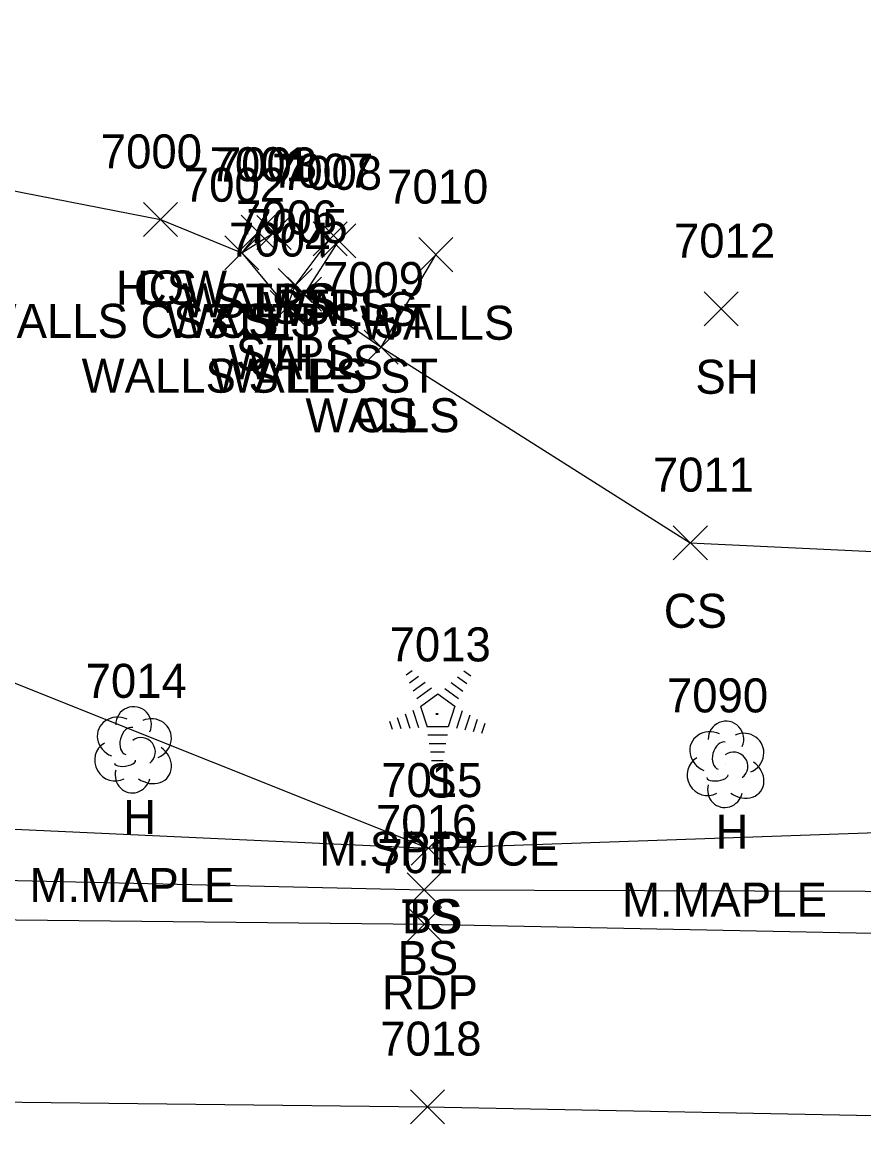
# Model space of a CAD drawing. Extents: x 1443912 to 1445411, y 621446 to 623693.
# Drawn here: x 1445082.7 to 1445132.2, y 622576.7 to 622641.6 of the extents above; entities that cross this region are included whole.
import ezdxf

# ---------------------------------------------------------------- set-up
doc = ezdxf.new("R2010")
doc.units = 0
for name, color, linetype in [('L_A', 7, 'Continuous'), ('L_C', 7, 'Continuous'), ('L_I', 7, 'Continuous'), ('L_TIC', 7, 'Continuous'), ('LBC', 7, 'Continuous'), ('LBF', 7, 'Continuous'), ('LELB', 7, 'Continuous'), ('LTC', 7, 'Continuous'), ('LTD', 7, 'Continuous'), ('LWS', 7, 'Continuous'), ('P_A', 7, 'Continuous'), ('P_I', 7, 'Continuous'), ('P_TIC', 7, 'Continuous'), ('PET', 7, 'Continuous'), ('PRC', 7, 'Continuous')]:
    doc.layers.add(name, color=color, linetype=linetype)

msp = doc.modelspace()

# ---------------------------------------------------------------- linework, layer by layer
at = {"layer": 'L_TIC'}
for points in [[(1445089.854, 622629.025), (1445091.854, 622631.025)], [(1445091.854, 622629.025), (1445089.854, 622631.025)], [(1445089.854, 622629.025), (1445091.854, 622631.025)], [(1445091.854, 622629.025), (1445089.854, 622631.025)], [(1445095.599, 622628.274), (1445097.599, 622630.274)], [(1445097.599, 622628.274), (1445095.599, 622630.274)], [(1445096.534, 622628.257), (1445098.534, 622630.257)], [(1445098.534, 622628.257), (1445096.534, 622630.257)], [(1445099.836, 622627.895), (1445101.836, 622629.895)], [(1445101.836, 622627.895), (1445099.836, 622629.895)], [(1445100.353, 622627.768), (1445102.353, 622629.768)], [(1445102.353, 622627.768), (1445100.353, 622629.768)], [(1445094.648, 622627.069), (1445096.648, 622629.069)], [(1445096.648, 622627.069), (1445094.648, 622629.069)], [(1445094.648, 622627.069), (1445096.648, 622629.069)], [(1445096.648, 622627.069), (1445094.648, 622629.069)], [(1445094.648, 622627.069), (1445096.648, 622629.069)], [(1445096.648, 622627.069), (1445094.648, 622629.069)], [(1445106.042, 622626.958), (1445108.042, 622628.958)], [(1445108.042, 622626.958), (1445106.042, 622628.958)], [(1445097.771, 622625.146), (1445099.771, 622627.146)], [(1445099.771, 622625.146), (1445097.771, 622627.146)], [(1445098.332, 622624.641), (1445100.332, 622626.641)], [(1445100.332, 622624.641), (1445098.332, 622626.641)], [(1445098.332, 622624.641), (1445100.332, 622626.641)], [(1445100.332, 622624.641), (1445098.332, 622626.641)], [(1445097.312, 622623.846), (1445099.312, 622625.846)], [(1445099.312, 622623.846), (1445097.312, 622625.846)], [(1445097.312, 622623.846), (1445099.312, 622625.846)], [(1445099.312, 622623.846), (1445097.312, 622625.846)], [(1445122.821, 622623.783), (1445124.821, 622625.783)], [(1445124.821, 622623.783), (1445122.821, 622625.783)], [(1445102.835, 622621.525), (1445104.835, 622623.525)], [(1445104.835, 622621.525), (1445102.835, 622623.525)], [(1445102.835, 622621.525), (1445104.835, 622623.525)], [(1445104.835, 622621.525), (1445102.835, 622623.525)], [(1445121.011, 622610.032), (1445123.011, 622612.032)], [(1445123.011, 622610.032), (1445121.011, 622612.032)], [(1445105.607, 622592.082), (1445107.607, 622594.082)], [(1445107.607, 622592.082), (1445105.607, 622594.082)], [(1445105.607, 622592.082), (1445107.607, 622594.082)], [(1445107.607, 622592.082), (1445105.607, 622594.082)], [(1445105.358, 622589.626), (1445107.358, 622591.626)], [(1445107.358, 622589.626), (1445105.358, 622591.626)]]:
    msp.add_lwpolyline(points, dxfattribs=at)
at = {"layer": 'LBC'}
msp.add_lwpolyline([(1445066.82, 622635.244), (1445068.456, 622634.393), (1445069.211, 622634.265), (1445090.854, 622630.025)], dxfattribs=at)
at = {"layer": 'LBF'}
for points in [[(1445095.648, 622628.069), (1445097.534, 622629.257)], [(1445098.312, 622624.846), (1445098.771, 622626.146), (1445100.836, 622628.895)]]:
    msp.add_lwpolyline(points, dxfattribs=at)
at = {"layer": 'LELB'}
for points in [[(1445032.656, 622641.625), (1445028.829, 622632.482), (1445026.782, 622624.174), (1445026.875, 622612.344), (1445034.973, 622594.496), (1445058.522, 622591.73), (1445106.358, 622590.626), (1445145.244, 622590.524), (1445168.822, 622591.089), (1445198.627, 622591.2), (1445245.014, 622591.72), (1445286.566, 622591.595), (1445300.707, 622591.322), (1445301.516, 622592.409)], [(1445069.211, 622634.265), (1445064.848, 622631.057), (1445063.076, 622628.999), (1445059.367, 622619.407), (1445056.944, 622619.214), (1445052.698, 622611.228), (1445068.69, 622608.203), (1445106.607, 622593.082)], [(1445090.854, 622630.025), (1445095.648, 622628.069)], [(1445040.06, 622622.698), (1445030.974, 622614.621), (1445043.651, 622596.971), (1445058.378, 622595.29), (1445106.607, 622593.082), (1445145.321, 622594.434), (1445169.592, 622596.135), (1445193.885, 622600.059), (1445198.253, 622615.727)], [(1445103.835, 622622.525), (1445122.011, 622611.032), (1445144.728, 622609.949), (1445183.268, 622615.731), (1445198.253, 622615.727), (1445206.434, 622600.749), (1445198.627, 622591.2)]]:
    msp.add_lwpolyline(points, dxfattribs=at)
at = {"layer": 'LTC'}
for p, q in [((1445105.296, 622603.265), (1445105.65, 622603.523)), ((1445105.505, 622602.8), (1445106.034, 622603.184)), ((1445108.323, 622603.158), (1445108.872, 622602.758)), ((1445108.694, 622603.506), (1445109.113, 622603.201)), ((1445105.715, 622602.334), (1445106.418, 622602.845)), ((1445105.924, 622601.868), (1445106.803, 622602.506)), ((1445107.58, 622602.461), (1445108.39, 622601.872)), ((1445107.952, 622602.809), (1445108.631, 622602.315)), ((1445106.149, 622601.413), (1445107.16, 622602.148)), ((1445107.16, 622602.148), (1445108.158, 622601.423)), ((1445105.239, 622600.978), (1445105.51, 622600.143)), ((1445105.694, 622601.194), (1445106.025, 622600.175)), ((1445106.149, 622601.413), (1445106.536, 622600.22)), ((1445108.158, 622601.423), (1445107.766, 622600.22)), ((1445108.595, 622601.152), (1445108.257, 622600.113)), ((1445104.328, 622600.545), (1445104.48, 622600.077)), ((1445104.783, 622600.761), (1445104.995, 622600.11)), ((1445109.04, 622600.902), (1445108.752, 622600.017)), ((1445109.484, 622600.652), (1445109.247, 622599.922)), ((1445109.928, 622600.401), (1445109.742, 622599.827)), ((1445107.766, 622600.22), (1445106.536, 622600.22)), ((1445107.728, 622599.72), (1445106.583, 622599.72)), ((1445107.644, 622599.22), (1445106.656, 622599.22)), ((1445107.56, 622598.72), (1445106.729, 622598.72)), ((1445107.477, 622598.22), (1445106.802, 622598.22))]:
    msp.add_line(p, q, dxfattribs=at)
at = {"layer": 'LTD'}
for p, q in [((1445089.23, 622598.915), (1445089.23, 622598.915)), ((1445089.23, 622598.915), (1445089.23, 622598.915)), ((1445124.062, 622598.06), (1445124.062, 622598.06)), ((1445124.062, 622598.06), (1445124.062, 622598.06))]:
    msp.add_line(p, q, dxfattribs=at)
for centre in [(1445089.277, 622600.349), (1445124.109, 622599.494)]:
    msp.add_arc(centre, 1.047, 335.52715, 180.95627, dxfattribs=at)
for centre, major_axis, ratio, start_param, end_param in [((1445088.438, 622599.582), (1.21, -0.512), 0.895232, 1.570796, 4.712389), ((1445090.272, 622599.499), (-1.141, -0.483), 0.949671, 1.570796, 4.712389), ((1445089.022, 622599.374), (-0.208, -0.792), 0.645439, 3.141593, 6.283185), ((1445089.73, 622598.749), (-0.5, 0.667), 0.989748, 3.141593, 6.283185), ((1445123.27, 622598.727), (1.21, -0.512), 0.895232, 1.570796, 4.712389), ((1445125.103, 622598.644), (-1.141, -0.483), 0.949671, 1.570796, 4.712389), ((1445088.147, 622598.207), (0.584, -1.042), 0.959034, 3.141593, 6.283185), ((1445090.23, 622598.082), (-1.09, 0.792), 0.841452, 1.570796, 4.712389), ((1445123.853, 622598.519), (-0.208, -0.792), 0.645439, 3.141593, 6.283185), ((1445122.979, 622597.352), (0.584, -1.042), 0.959034, 3.141593, 6.283185), ((1445124.562, 622597.894), (-0.5, 0.667), 0.989748, 3.141593, 6.283185), ((1445088.772, 622598.165), (-0.625, -0.083), 0.423636, 0, 3.141593), ((1445125.062, 622597.227), (-1.09, 0.792), 0.841452, 1.570796, 4.712389), ((1445089.231, 622597.415), (0.265, 1.061), 0.942809, 1.570796, 4.712389), ((1445123.604, 622597.31), (-0.625, -0.083), 0.423636, 0, 3.141593), ((1445124.062, 622596.56), (0.265, 1.061), 0.942809, 1.570796, 4.712389)]:
    msp.add_ellipse(centre, major_axis=major_axis, ratio=ratio, start_param=start_param, end_param=end_param, dxfattribs=at)
at = {"layer": 'LWS'}
for points in [[(1445096.599, 622629.274), (1445095.648, 622628.069), (1445098.312, 622624.846), (1445099.332, 622625.641), (1445101.353, 622628.768)], [(1445099.332, 622625.641), (1445103.835, 622622.525), (1445107.042, 622627.958)]]:
    msp.add_lwpolyline(points, dxfattribs=at)
at = {"layer": 'P_TIC'}
for points in [[(1445105.387, 622587.611), (1445107.387, 622589.611)], [(1445107.387, 622587.611), (1445105.387, 622589.611)], [(1445105.555, 622576.89), (1445107.555, 622578.89)], [(1445107.555, 622576.89), (1445105.555, 622578.89)]]:
    msp.add_lwpolyline(points, dxfattribs=at)
at = {"layer": 'PET'}
msp.add_lwpolyline([(1444828.325, 622597.96), (1444848.504, 622596.752), (1444898.46, 622594.677), (1444911.129, 622594.321), (1444955.703, 622592.454), (1444994.25, 622591.157), (1445024.916, 622590.298), (1445058.354, 622589.126), (1445106.387, 622588.611), (1445145.413, 622587.835), (1445199.354, 622587.761), (1445245.806, 622587.569), (1445289.735, 622586.867), (1445302.68, 622587.056), (1445331.619, 622586.772), (1445351.379, 622587.403), (1445404.24, 622586.997)], dxfattribs=at)
at = {"layer": 'PRC'}
msp.add_lwpolyline([(1444773.111, 622588.757), (1444790.079, 622588.196), (1444813.693, 622587.068), (1444848.471, 622586.579), (1444897.837, 622583.54), (1444932.228, 622582.395), (1444986.667, 622580.693), (1445025.716, 622579.484), (1445065.673, 622578.343), (1445106.555, 622577.89), (1445145.901, 622577.113), (1445204.597, 622577.216), (1445219.997, 622576.877), (1445261.162, 622576.439), (1445312.233, 622575.287), (1445358.841, 622575.991), (1445405.048, 622576.003)], dxfattribs=at)

# ---------------------------------------------------------------- texts
at = {"layer": 'L_A'}
for s, p in [('HOW', (1445088.239, 622625.025)), ('CS', (1445089.295, 622625.025)), ('WALLS', (1445092.143, 622624.274)), ('STPS', (1445094.054, 622624.257)), ('WALLS', (1445096.897, 622623.768)), ('STPS', (1445097.356, 622623.895)), ('WALLS CS3 STPS ST', (1445079.877, 622623.069)), ('WALLS', (1445091.192, 622623.069)), ('CS', (1445094.089, 622623.069)), ('WALLS', (1445102.586, 622622.958)), ('STPS', (1445095.291, 622621.146)), ('WALLS', (1445094.875, 622620.641)), ('WALLS', (1445094.875, 622620.641)), ('WALLS STPS ST', (1445086.225, 622619.846)), ('WALLS', (1445093.855, 622619.846)), ('SH', (1445122.309, 622619.783)), ('WALLS', (1445099.378, 622617.525)), ('CS', (1445102.276, 622617.525)), ('CS', (1445120.452, 622606.032)), ('S', (1445106.486, 622596.057)), ('H', (1445088.663, 622593.915)), ('H', (1445123.495, 622593.06)), ('TS', (1445105.016, 622588.082)), ('BS', (1445105.048, 622588.082)), ('BS', (1445104.799, 622585.626))]:
    msp.add_text(s, height=2, dxfattribs=at).set_placement(p)
at = {"layer": 'L_C'}
for s, p in [('M.SPRUCE', (1445100.187, 622592.057)), ('M.MAPLE', (1445083.167, 622589.915)), ('M.MAPLE', (1445117.999, 622589.06))]:
    msp.add_text(s, height=2, dxfattribs=at).set_placement(p)
at = {"layer": 'L_I'}
for s, p in [('7000', (1445087.35, 622633.025)), ('7000', (1445087.35, 622633.025)), ('7001', (1445093.749, 622632.274)), ('7003', (1445094.117, 622632.257)), ('7007', (1445097.419, 622631.895)), ('7008', (1445097.936, 622631.768)), ('7002', (1445092.231, 622631.069)), ('7002', (1445092.231, 622631.069)), ('7002', (1445092.231, 622631.069)), ('7010', (1445104.184, 622630.958)), ('7006', (1445095.299, 622629.146)), ('7005', (1445095.914, 622628.641)), ('7005', (1445095.914, 622628.641)), ('7004', (1445094.895, 622627.846)), ('7004', (1445094.895, 622627.846)), ('7012', (1445121.05, 622627.783)), ('7009', (1445100.409, 622625.525)), ('7009', (1445100.409, 622625.525)), ('7011', (1445119.807, 622614.032)), ('7013', (1445104.329, 622604.057)), ('7014', (1445086.459, 622601.915)), ('7090', (1445120.637, 622601.06)), ('7015', (1445103.835, 622596.082)), ('7015', (1445103.835, 622596.082)), ('7016', (1445103.531, 622593.626))]:
    msp.add_text(s, height=2, dxfattribs=at).set_placement(p)
at = {"layer": 'LTC'}
msp.add_text('.', height=1.037, rotation=270, dxfattribs=at).set_placement((1445107.043, 622601.161))
at = {"layer": 'P_A'}
msp.add_text('RDP', height=2, dxfattribs=at).set_placement((1445103.875, 622583.611))
at = {"layer": 'P_I'}
for s, p in [('7017', (1445103.616, 622591.611)), ('7018', (1445103.784, 622580.89))]:
    msp.add_text(s, height=2, dxfattribs=at).set_placement(p)

doc.saveas('drawing.dxf')
